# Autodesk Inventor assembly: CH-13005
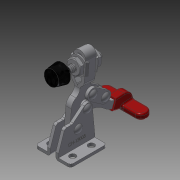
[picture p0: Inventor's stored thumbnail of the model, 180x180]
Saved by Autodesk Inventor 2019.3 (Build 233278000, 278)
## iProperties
Company: Î¢ÈíÖÐ¹ú
Created: 2012-09
Part Number: CH-13005
Material: Ogólny
Description: STEP AP203
Document SubType Name: Assembly
Designer: CADENGINEERING4
Stock Number: DOCISK PIONOWY
Sending System: SolidWorks 2010
Preprocessor: SwSTEP 2.0
Title: CH-13005.STEP
Author: Î¢ÈíÓÃ»§
Revision Number: ÈÎºÎ
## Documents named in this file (9)
- D:\Vault_2016\Projekty\Clamptek\STRONA\Vertical toggle clamp\CH-13005\CH-13005_OTWARTY.iam
- D:\Vault_2016\Projekty\Clamptek\STRONA\Vertical toggle clamp\CH-13005\CH-13005-04 CONNECTING-PLATE.ipt
- D:\Vault_2016\Projekty\Clamptek\STRONA\Vertical toggle clamp\CH-13005\CH-13005-03 T-HANDLE.ipt
- D:\Vault_2016\Projekty\Clamptek\STRONA\Vertical toggle clamp\CH-13005\CH-13005-01 FLANGED BASE.ipt
- D:\Vault_2016\Projekty\Clamptek\STRONA\Vertical toggle clamp\CH-13005\CH-13005-02 U-BAR.ipt
- D:\Vault_2016\Projekty\Clamptek\STRONA\Vertical toggle clamp\CH-13005\CH-FW-100.ipt
- D:\Vault_2016\Projekty\Clamptek\STRONA\Vertical toggle clamp\CH-13005\CH-13005-05 .ipt
- D:\Vault_2016\Projekty\Clamptek\STRONA\Vertical toggle clamp\CH-13005\CH-FC-10138 SPINDLE SUPPLIED.ipt
- D:\Vault_2016\Projekty\Clamptek\STRONA\Vertical toggle clamp\CH-13005\CH-FC-10138 Nut.ipt
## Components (14 placed, 14 different names)
1. CH-13005-04 CONNECTING-PLATE_1 — Zestawiające:5, Zestawiające:6, Zestawiające:10, Zestawiające:17, Zestawiające:18
2. CH-13005-03 T-HANDLE_2 — Zestawiające:2, Zestawiające:3, Zestawiające:6, Zestawiające:8, Zestawiające:30
3. CH-13005-01 FLANGED BASE_3 — Zestawiające:1, Zestawiające:2, Zestawiające:7, Zestawiające:8, Zestawiające:11, Zestawiające:12, Zestawiające:13, Zestawiające:14
4. CH-13005-02 U-BAR_4 — Zestawiające:1, Zestawiające:4, Zestawiające:5, Zestawiające:7, Zestawiające:9, Zestawiające:10, Zestawiające:21, Zestawiające:22, Zestawiające:23, Zestawiające:24, Kątowe:1, Kątowe:2, Zestawiające:30
5. CH-13005-04 CONNECTING-PLATE_5 — Zestawiające:3, Zestawiające:4, Zestawiające:9, Zestawiające:15, Zestawiające:16
6. CH-FW-100_6 — Zestawiające:20, Zestawiające:21, Zestawiające:23, Zestawiające:24, Zestawiające:26, Zestawiające:27, Kątowe:1
7. CH-13005-05 _7 — Zestawiające:12, Zestawiające:13
8. CH-FC-10138 SPINDLE SUPPLIED_8 — Zestawiające:29, Równoległe:1
9. CH-13005-05 _9 — Zestawiające:16, Zestawiające:18
10. CH-13005-05 _10 — Zestawiające:15, Zestawiające:17
11. CH-13005-05 _11 — Zestawiające:11, Zestawiające:14
12. CH-FC-10138 Nut_12 — Zestawiające:26, Zestawiające:27
13. CH-FW-100_13 — Zestawiające:20, Zestawiające:22, Zestawiające:25, Zestawiające:28, Równoległe:1, Kątowe:2
14. CH-FC-10138 Nut_14 — Zestawiające:25, Zestawiające:28, Zestawiające:29
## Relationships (32: Mate 29, Angle 2, Flush 1)
- Zestawiające:1 [Mate]: CH-13005-01 FLANGED BASE_3 ↔ CH-13005-02 U-BAR_4
- Zestawiające:2 [Mate]: CH-13005-03 T-HANDLE_2 ↔ CH-13005-01 FLANGED BASE_3
- Zestawiające:3 [Mate]: CH-13005-03 T-HANDLE_2 ↔ CH-13005-04 CONNECTING-PLATE_5
- Zestawiające:4 [Mate]: CH-13005-02 U-BAR_4 ↔ CH-13005-04 CONNECTING-PLATE_5
- Zestawiające:5 [Mate]: CH-13005-04 CONNECTING-PLATE_1 ↔ CH-13005-02 U-BAR_4
- Zestawiające:6 [Mate]: CH-13005-04 CONNECTING-PLATE_1 ↔ CH-13005-03 T-HANDLE_2
- Zestawiające:7 [Mate]: CH-13005-01 FLANGED BASE_3 ↔ CH-13005-02 U-BAR_4
- Zestawiające:8 [Mate]: CH-13005-03 T-HANDLE_2 ↔ CH-13005-01 FLANGED BASE_3
- Zestawiające:9 [Mate]: CH-13005-02 U-BAR_4 ↔ CH-13005-04 CONNECTING-PLATE_5
- Zestawiające:10 [Mate]: CH-13005-04 CONNECTING-PLATE_1 ↔ CH-13005-02 U-BAR_4
- Zestawiające:11 [Mate]: CH-13005-01 FLANGED BASE_3 ↔ CH-13005-05 _11
- Zestawiające:12 [Mate]: CH-13005-01 FLANGED BASE_3 ↔ CH-13005-05 _7
- Zestawiające:13 [Mate]: CH-13005-01 FLANGED BASE_3 ↔ CH-13005-05 _7
- Zestawiające:14 [Mate]: CH-13005-01 FLANGED BASE_3 ↔ CH-13005-05 _11
- Zestawiające:15 [Mate]: CH-13005-04 CONNECTING-PLATE_5 ↔ CH-13005-05 _10
- Zestawiające:16 [Mate]: CH-13005-04 CONNECTING-PLATE_5 ↔ CH-13005-05 _9
- Zestawiające:17 [Mate]: CH-13005-04 CONNECTING-PLATE_1 ↔ CH-13005-05 _10
- Zestawiające:18 [Mate]: CH-13005-04 CONNECTING-PLATE_1 ↔ CH-13005-05 _9
- Zestawiające:20 [Mate]: CH-FW-100_6 ↔ CH-FW-100_13
- Zestawiające:21 [Mate]: CH-13005-02 U-BAR_4 ↔ CH-FW-100_6
- Zestawiające:22 [Mate]: CH-13005-02 U-BAR_4 ↔ CH-FW-100_13
- Zestawiające:23 [Mate]: CH-13005-02 U-BAR_4 ↔ CH-FW-100_6
- Zestawiające:24 [Mate]: CH-13005-02 U-BAR_4 ↔ CH-FW-100_6
- Zestawiające:25 [Mate]: CH-FW-100_13 ↔ CH-FC-10138 Nut_14
- Zestawiające:26 [Mate]: CH-FW-100_6 ↔ CH-FC-10138 Nut_12
- Zestawiające:27 [Mate]: CH-FW-100_6 ↔ CH-FC-10138 Nut_12
- Zestawiające:28 [Mate]: CH-FW-100_13 ↔ CH-FC-10138 Nut_14
- Zestawiające:29 [Mate]: CH-FC-10138 SPINDLE SUPPLIED_8 ↔ CH-FC-10138 Nut_14
- Równoległe:1 [Flush]: CH-FC-10138 SPINDLE SUPPLIED_8 ↔ CH-FW-100_13
- Kątowe:1 [Angle]: CH-13005-02 U-BAR_4 ↔ CH-FW-100_6
- Kątowe:2 [Angle]: CH-13005-02 U-BAR_4 ↔ CH-FW-100_13
- Zestawiające:30 [Mate]: CH-13005-03 T-HANDLE_2 ↔ CH-13005-02 U-BAR_4
